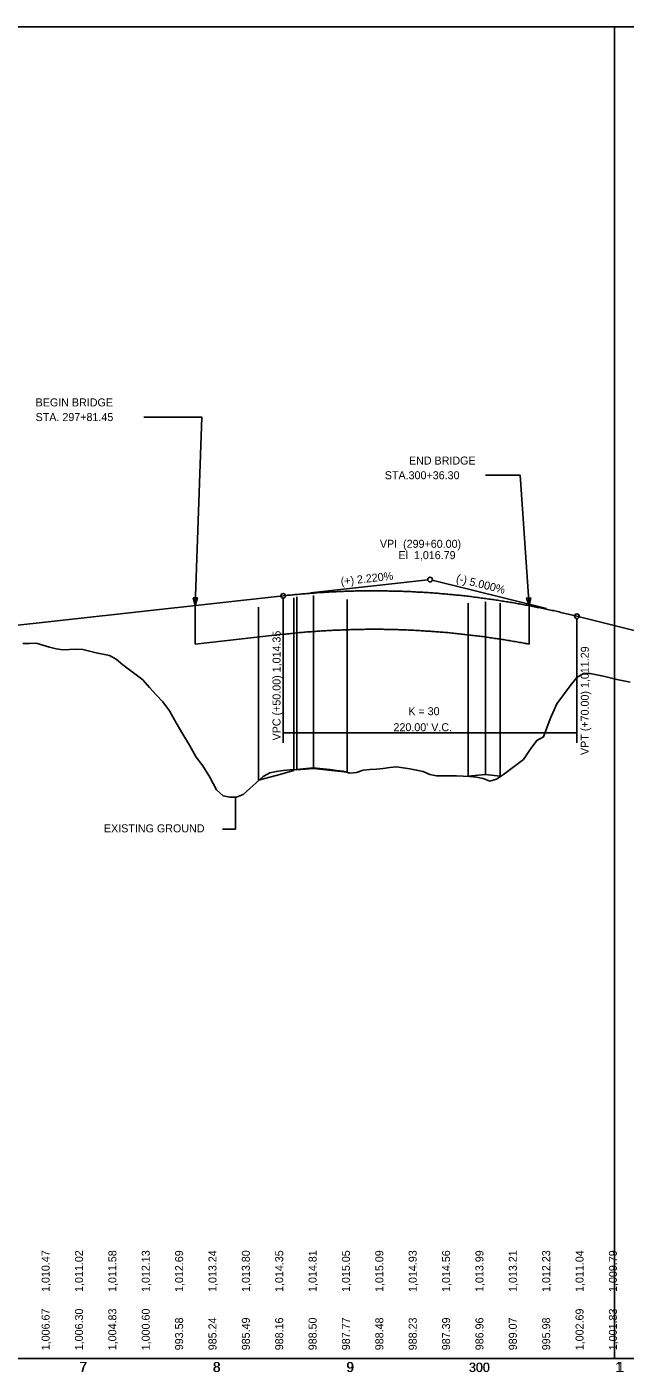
# Model space of a CAD drawing. Extents: x 112 to 16977479, y 1011 to 12562669.
# Drawn here: x 16974038 to 16974487, y 12561659 to 12562667 of the extents above; entities that cross this region are included whole.
import ezdxf

# ---------------------------------------------------------------- set-up
doc = ezdxf.new("R2010")
doc.units = 0
for name, color, linetype in [('Default', 7, 'Continuous'), ('RD_DDB_Ex_Tx', 7, 'Continuous'), ('RD_DDB_GradeTX', 7, 'Continuous'), ('RD_DDB_PI', 7, 'Continuous'), ('RD_DDB_Profile_EX', 7, 'Continuous'), ('RD_DDB_Profile_PR', 7, 'Continuous'), ('RD_DDB_StaTX', 7, 'Continuous'), ('RD_DDB_StripGrade_EX', 7, 'Continuous'), ('RD_DDB_StripGrade_PR', 7, 'Continuous'), ('RD_DDB_VCLbl', 7, 'Continuous'), ('RD_GPK_Profile_Cell', 7, 'Continuous'), ('RD_PD_Bridge', 7, 'Continuous'), ('RD_SHT_TX', 7, 'Continuous'), ('RD_Sketch1', 7, 'Continuous')]:
    doc.layers.add(name, color=color, linetype=linetype)

msp = doc.modelspace()

# ---------------------------------------------------------------- linework, layer by layer
at = {"layer": 'Default'}
for points in [[(16972978.7, 12561668.9), (16974478.7, 12561668.9), (16974478.7, 12562667.2), (16972978.7, 12562667.2)], [(16974478.7, 12561668.9), (16975978.7, 12561668.9), (16975978.7, 12562667.2), (16974478.7, 12562667.2)]]:
    msp.add_lwpolyline(points, close=True, dxfattribs=at)
at = {"layer": 'RD_DDB_Ex_Tx'}
for p, q in [((16974194.7, 12562065.9), (16974194.7, 12562089.8)), ((16974184.9, 12562065.9), (16974194.7, 12562065.9))]:
    msp.add_line(p, q, dxfattribs=at)
at = {"layer": 'RD_DDB_PI'}
for p, q in [((16974250.9, 12562243), (16974338.7, 12562252.7)), ((16974427.7, 12562231.1), (16974342.1, 12562252.5))]:
    msp.add_line(p, q, dxfattribs=at)
msp.add_circle((16974340.4, 12562252.9), 1.75, dxfattribs=at)
at = {"layer": 'RD_DDB_Profile_EX'}
for points in [[(16974035.3, 12562205), (16974040.3, 12562205), (16974045.3, 12562205.2), (16974050.3, 12562203.8), (16974055.3, 12562202.3), (16974060.3, 12562201), (16974065.3, 12562200.3), (16974070.3, 12562200.4), (16974075.3, 12562200.6), (16974080.3, 12562200.4), (16974085.3, 12562199.3), (16974090.3, 12562198), (16974095.3, 12562196.9), (16974100.3, 12562195.9), (16974105.3, 12562193.2), (16974110.3, 12562189.1), (16974115.3, 12562185.2)], [(16974115.3, 12562185.2), (16974120.3, 12562181.5), (16974125.3, 12562177.7), (16974130.3, 12562172.1), (16974135.3, 12562166.6), (16974140.3, 12562161.2), (16974145.3, 12562154.6), (16974150.3, 12562145.6), (16974155.3, 12562137.1), (16974160.3, 12562128.7), (16974165.3, 12562119.8), (16974170.3, 12562113.3), (16974175.3, 12562104.7), (16974180.3, 12562095.3), (16974185.3, 12562090.7), (16974190.3, 12562089.8), (16974195.3, 12562089.9), (16974200.3, 12562091.9), (16974205.3, 12562096.3), (16974210.3, 12562100.7), (16974215.3, 12562105.3), (16974220.3, 12562108.1), (16974225.3, 12562109.1), (16974230.3, 12562109.7), (16974235.3, 12562110.2), (16974240.3, 12562110.6), (16974245.3, 12562111.1), (16974250.3, 12562111.5), (16974255.3, 12562111.4), (16974260.3, 12562111), (16974265.3, 12562110.5), (16974270.3, 12562109.8), (16974275.3, 12562109.2), (16974280.3, 12562107.8), (16974285.3, 12562108.2), (16974290.3, 12562109.9), (16974295.3, 12562110.4), (16974300.3, 12562110.8), (16974305.3, 12562111.3), (16974310.3, 12562111.9), (16974315.3, 12562112.4), (16974320.3, 12562111.8), (16974325.3, 12562111), (16974330.3, 12562110.1), (16974335.3, 12562109), (16974340.3, 12562106.9), (16974345.3, 12562105.9), (16974350.3, 12562105.8), (16974355.3, 12562105.9), (16974360.3, 12562105.8), (16974365.3, 12562105.6), (16974370.3, 12562105.3), (16974375.3, 12562104.7), (16974380.3, 12562103.8), (16974385.3, 12562101.7), (16974390.3, 12562103.2), (16974395.3, 12562106.7), (16974400.3, 12562110.5), (16974405.3, 12562114.2), (16974410.3, 12562117.9), (16974415.3, 12562125.4), (16974420.3, 12562132.3), (16974425.3, 12562134.9), (16974430.3, 12562148.6), (16974435.3, 12562159.7), (16974440.3, 12562166.6), (16974445.3, 12562173.2), (16974450.3, 12562179.6), (16974455.3, 12562182.4), (16974460.3, 12562182.4), (16974465.3, 12562181.5), (16974470.3, 12562180.6), (16974475.3, 12562179.3), (16974480.3, 12562178.1), (16974485.3, 12562177), (16974490.3, 12562175.9)]]:
    msp.add_lwpolyline(points, dxfattribs=at)
at = {"layer": 'RD_DDB_Profile_PR'}
for p, q in [((16973885.4, 12562202.4), (16974230.4, 12562240.7)), ((16974450.4, 12562225.4), (16974495.4, 12562214.2))]:
    msp.add_line(p, q, dxfattribs=at)
msp.add_spline([(16974230.4, 12562240.7), (16974234.8, 12562241.2), (16974239.2, 12562241.6), (16974243.6, 12562242), (16974248, 12562242.4), (16974252.4, 12562242.7), (16974256.8, 12562243.1), (16974261.2, 12562243.3), (16974265.6, 12562243.6), (16974270, 12562243.8), (16974274.4, 12562244), (16974278.8, 12562244.2), (16974283.2, 12562244.3), (16974287.6, 12562244.4), (16974292, 12562244.4), (16974296.4, 12562244.5), (16974300.8, 12562244.4), (16974305.2, 12562244.4), (16974309.6, 12562244.3), (16974314, 12562244.2), (16974318.4, 12562244.1), (16974322.8, 12562244), (16974327.2, 12562243.8), (16974331.6, 12562243.5), (16974336, 12562243.3), (16974340.4, 12562243), (16974344.8, 12562242.7), (16974349.2, 12562242.3), (16974353.6, 12562241.9), (16974358, 12562241.5), (16974362.4, 12562241.1), (16974366.8, 12562240.6), (16974371.2, 12562240.1), (16974375.6, 12562239.5), (16974380, 12562238.9), (16974384.4, 12562238.3), (16974388.8, 12562237.7), (16974393.2, 12562237), (16974397.6, 12562236.3), (16974402, 12562235.6), (16974406.4, 12562234.8), (16974410.8, 12562234), (16974415.2, 12562233.2), (16974419.6, 12562232.3), (16974424, 12562231.4), (16974428.4, 12562230.5), (16974432.8, 12562229.6), (16974437.2, 12562228.6), (16974441.6, 12562227.5), (16974446, 12562226.5), (16974450.4, 12562225.4)], degree=3, dxfattribs=at)
at = {"layer": 'RD_DDB_VCLbl'}
for p, q in [((16974230.4, 12562130.4), (16974230.4, 12562239)), ((16974450.4, 12562130.4), (16974450.4, 12562223.7)), ((16974230.4, 12562137.9), (16974450.4, 12562137.9))]:
    msp.add_line(p, q, dxfattribs=at)
for centre in [(16974230.4, 12562240.7), (16974450.4, 12562225.4)]:
    msp.add_circle(centre, 1.75, dxfattribs=at)
at = {"layer": 'RD_GPK_Profile_Cell'}
msp.add_line((16973115.3, 12561668.9), (16977337.9, 12561668.9), dxfattribs=at)
at = {"layer": 'RD_PD_Bridge'}
for p, q in [((16974164.4, 12562204.5), (16974164.4, 12562233.4)), ((16974414.6, 12562204.5), (16974414.6, 12562233.3)), ((16974164.4, 12562204.5), (16974230.4, 12562211.9))]:
    msp.add_line(p, q, dxfattribs=at)
msp.add_spline([(16974230.4, 12562211.9), (16974234.8, 12562212.3), (16974239.2, 12562212.8), (16974243.6, 12562213.2), (16974248, 12562213.6), (16974252.4, 12562213.9), (16974256.8, 12562214.2), (16974261.2, 12562214.5), (16974265.6, 12562214.7), (16974270, 12562215), (16974274.4, 12562215.1), (16974278.8, 12562215.3), (16974283.2, 12562215.4), (16974287.6, 12562215.5), (16974292, 12562215.6), (16974296.4, 12562215.6), (16974300.8, 12562215.6), (16974305.2, 12562215.6), (16974309.6, 12562215.5), (16974314, 12562215.4), (16974318.4, 12562215.3), (16974322.8, 12562215.1), (16974327.2, 12562214.9), (16974331.6, 12562214.7), (16974336, 12562214.4), (16974340.4, 12562214.1), (16974344.8, 12562213.8), (16974349.2, 12562213.5), (16974353.6, 12562213.1), (16974358, 12562212.7), (16974362.4, 12562212.2), (16974366.8, 12562211.7), (16974371.2, 12562211.2), (16974375.6, 12562210.7), (16974380, 12562210.1), (16974384.4, 12562209.5), (16974388.8, 12562208.8), (16974393.2, 12562208.2), (16974397.6, 12562207.5), (16974402, 12562206.7), (16974406.4, 12562206), (16974410.8, 12562205.2), (16974414.6, 12562204.5)], degree=3, dxfattribs=at)
at = {"layer": 'RD_SHT_TX'}
for points in [[(16974126.1, 12562374.7), (16974169.4, 12562374.7), (16974164.4, 12562233.4)], [(16974381.9, 12562331.1), (16974407.8, 12562331.1), (16974414.6, 12562233.3)]]:
    msp.add_lwpolyline(points, dxfattribs=at)
for points in [[(16974163, 12562239.2), (16974164.4, 12562233.4), (16974166.1, 12562239.1)], [(16974415.8, 12562239.2), (16974414.6, 12562233.3), (16974412.7, 12562239)]]:
    msp.add_lwpolyline(points, close=True, dxfattribs=at)
at = {"layer": 'RD_Sketch1'}
for p, q in [((16974238.3, 12562234.3), (16974238.3, 12562239.3)), ((16974240.5, 12562234.9), (16974240.5, 12562239.9)), ((16974253.2, 12562235.9), (16974253.2, 12562240.9)), ((16974253.2, 12562207.2), (16974253.2, 12562235.9)), ((16974278.4, 12562233), (16974278.4, 12562238)), ((16974382, 12562231.3), (16974382, 12562236.3)), ((16974211.9, 12562227.1), (16974211.9, 12562232.1)), ((16974211.9, 12562198.3), (16974211.9, 12562227.1)), ((16974238.3, 12562205.6), (16974238.3, 12562234.3)), ((16974240.5, 12562206.1), (16974240.5, 12562234.9)), ((16974278.4, 12562204.3), (16974278.4, 12562233)), ((16974369, 12562230.2), (16974369, 12562235.2)), ((16974369, 12562201.5), (16974369, 12562230.2)), ((16974382, 12562202.6), (16974382, 12562231.3)), ((16974393, 12562230.2), (16974393, 12562235.2)), ((16974393, 12562201.5), (16974393, 12562230.2)), ((16974238.3, 12562194.7), (16974238.3, 12562205.6)), ((16974240.5, 12562195.3), (16974240.5, 12562206.1)), ((16974253.2, 12562196.3), (16974253.2, 12562207.2)), ((16974211.9, 12562187.5), (16974211.9, 12562198.3)), ((16974253.2, 12562111.3), (16974253.2, 12562196.3)), ((16974278.4, 12562193.4), (16974278.4, 12562204.3)), ((16974369, 12562190.6), (16974369, 12562201.5)), ((16974382, 12562191.7), (16974382, 12562202.6)), ((16974393, 12562190.6), (16974393, 12562201.5)), ((16974211.9, 12562102.5), (16974211.9, 12562187.5)), ((16974238.3, 12562109.7), (16974238.3, 12562194.7)), ((16974240.5, 12562110.3), (16974240.5, 12562195.3)), ((16974278.4, 12562108.4), (16974278.4, 12562193.4)), ((16974369, 12562105.6), (16974369, 12562190.6)), ((16974382, 12562106.7), (16974382, 12562191.7)), ((16974393, 12562105.6), (16974393, 12562190.6)), ((16974211.9, 12562102.5), (16974225.2, 12562106)), ((16974225.2, 12562106), (16974238.3, 12562109.7)), ((16974240.5, 12562110.3), (16974253.2, 12562111.3)), ((16974253.2, 12562111.3), (16974278.4, 12562108.4)), ((16974369, 12562105.6), (16974382, 12562106.7)), ((16974382, 12562106.7), (16974393, 12562105.6))]:
    msp.add_line(p, q, dxfattribs=at)

# ---------------------------------------------------------------- texts
at = {"layer": 'RD_DDB_Ex_Tx'}
msp.add_text('EXISTING GROUND', height=6, dxfattribs=at).set_placement((16974096.1, 12562063.4))
at = {"layer": 'RD_DDB_GradeTX'}
for s, rotation, p in [('(+) 2.220%', 6.3339, (16974273.8, 12562248.5)), ('(-) 5.000%', 345.9641, (16974359.5, 12562251.2))]:
    msp.add_text(s, height=6, rotation=rotation, dxfattribs=at).set_placement(p)
at = {"layer": 'RD_DDB_PI'}
for s, p in [('VPI  (299+60.00)', (16974302.8, 12562276.7)), ('El  1,016.79', (16974316.7, 12562268.2))]:
    msp.add_text(s, height=6, dxfattribs=at).set_placement(p)
at = {"layer": 'RD_DDB_StaTX'}
for s, height, p in [('7', 7.5, (16974077.6, 12561658.9)), ('7', 7.5, (16974077.6, 12561658.9)), ('7', 7.5, (16974078, 12561658.9)), ('8', 7.5, (16974177.6, 12561658.9)), ('8', 7.5, (16974177.6, 12561658.9)), ('8', 7.5, (16974178, 12561658.9)), ('9', 7.5, (16974277.6, 12561658.9)), ('9', 7.5, (16974277.6, 12561658.9)), ('9', 7.5, (16974278, 12561658.9)), ('300', 7, (16974369.4, 12561658.9)), ('300', 7, (16974369.4, 12561658.9)), ('300', 7, (16974369.7, 12561658.9)), ('1', 7.5, (16974479.1, 12561658.9)), ('1', 7.5, (16974479.1, 12561658.9)), ('1', 7.5, (16974480.4, 12561658.9))]:
    msp.add_text(s, height=height, dxfattribs=at).set_placement(p)
at = {"layer": 'RD_DDB_StripGrade_EX'}
for s, p in [('1,006.67', (16974055.4, 12561675.2)), ('1,006.30', (16974080.4, 12561675.2)), ('1,004.83', (16974105.4, 12561675.2)), ('1,000.60', (16974130.4, 12561675.2)), ('1,002.69', (16974455.4, 12561675.2)), ('1,001.83', (16974480.4, 12561675.2)), ('993.58', (16974155.4, 12561675.2)), ('985.24', (16974180.4, 12561675.2)), ('985.49', (16974205.4, 12561675.2)), ('988.16', (16974230.4, 12561675.2)), ('988.50', (16974255.4, 12561675.2)), ('987.77', (16974280.4, 12561675.2)), ('988.48', (16974305.4, 12561675.2)), ('988.23', (16974330.4, 12561675.2)), ('987.39', (16974355.4, 12561675.2)), ('986.96', (16974380.4, 12561675.2)), ('989.07', (16974405.4, 12561675.2)), ('995.98', (16974430.4, 12561675.2))]:
    msp.add_text(s, height=6, rotation=90, dxfattribs=at).set_placement(p)
at = {"layer": 'RD_DDB_StripGrade_PR'}
for s, p in [('1,010.47', (16974055.4, 12561718.9)), ('1,011.02', (16974080.4, 12561718.9)), ('1,011.58', (16974105.4, 12561718.9)), ('1,012.13', (16974130.4, 12561718.9)), ('1,012.69', (16974155.4, 12561718.9)), ('1,013.24', (16974180.4, 12561718.9)), ('1,013.80', (16974205.4, 12561718.9)), ('1,014.35', (16974230.4, 12561718.9)), ('1,014.81', (16974255.4, 12561718.9)), ('1,015.05', (16974280.4, 12561718.9)), ('1,015.09', (16974305.4, 12561718.9)), ('1,014.93', (16974330.4, 12561718.9)), ('1,014.56', (16974355.4, 12561718.9)), ('1,013.99', (16974380.4, 12561718.9)), ('1,013.21', (16974405.4, 12561718.9)), ('1,012.23', (16974430.4, 12561718.9)), ('1,011.04', (16974455.4, 12561718.9)), ('1,009.79', (16974480.4, 12561718.9))]:
    msp.add_text(s, height=6, rotation=90, dxfattribs=at).set_placement(p)
at = {"layer": 'RD_DDB_VCLbl'}
for s, p in [('VPC (+50.00) 1,014.35', (16974228.4, 12562132.3)), ('VPT (+70.00) 1,011.29', (16974459.3, 12562121.4))]:
    msp.add_text(s, height=6, rotation=90, dxfattribs=at).set_placement(p)
for s, p in [('K = 30', (16974324.1, 12562151.2)), ("220.00' V.C.", (16974313, 12562139.2))]:
    msp.add_text(s, height=6, dxfattribs=at).set_placement(p)
at = {"layer": 'RD_SHT_TX'}
for s, p in [('BEGIN BRIDGE', (16974044.9, 12562382.7)), ('STA. 297+81.45', (16974044.9, 12562371.7))]:
    msp.add_text(s, height=6, rotation=360, dxfattribs=at).set_placement(p)
for s, p in [('END BRIDGE', (16974324.6, 12562339.1)), ('STA.300+36.30', (16974306.5, 12562328.1))]:
    msp.add_text(s, height=6, dxfattribs=at).set_placement(p)

doc.saveas('drawing.dxf')
